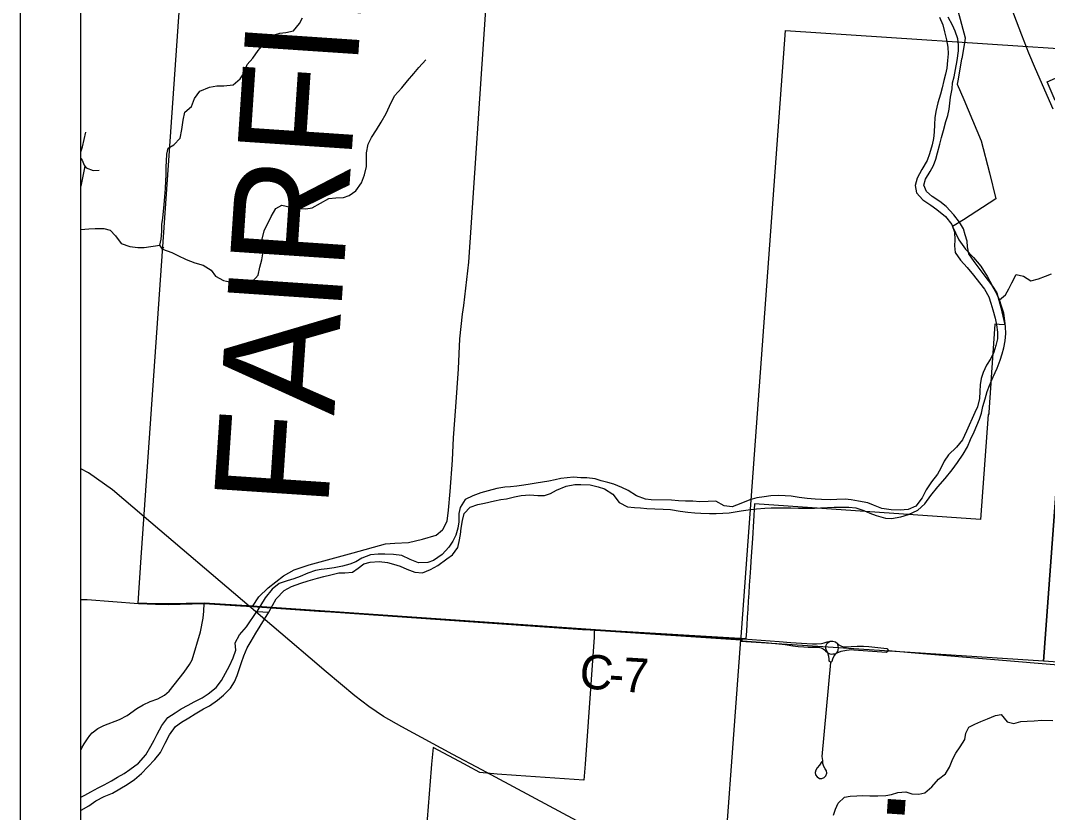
# Model space of a CAD drawing. Extents: x 0 to 34, y 0 to 26.1.
# Drawn here: x 23.417 to 25.117, y 15.919 to 17.231 of the extents above; entities that cross this region are included whole.
import ezdxf

# ---------------------------------------------------------------- set-up
doc = ezdxf.new("R2010")
doc.units = 0
for name, color, linetype in [('GM_X_City_Street', 7, 'Continuous'), ('GM_X_County', 7, 'Continuous'), ('GM_X_County_Road', 7, 'Continuous'), ('GM_X_County_Road_Text', 7, 'Continuous'), ('GM_X_County_Text', 7, 'Continuous'), ('GM_X_Minor_River', 7, 'Continuous'), ('GM_X_Rail_Line', 7, 'Continuous'), ('GM_X_Section', 7, 'Continuous'), ('GM_X_State_Route', 7, 'Continuous'), ('GM_X_Township_Road', 7, 'Continuous'), ('SC_Scratch1', 7, 'Continuous'), ('SH_Data', 7, 'Continuous')]:
    doc.layers.add(name, color=color, linetype=linetype)

msp = doc.modelspace()

# ---------------------------------------------------------------- linework, layer by layer
at = {"layer": 'GM_X_City_Street'}
for p, q in [((23.5233, 16.9894), (23.5167, 16.9562)), ((23.7209, 16.2653), (23.7808, 16.2616)), ((23.7808, 16.2616), (23.7908, 16.261)), ((23.7908, 16.261), (23.8007, 16.2604)), ((23.8007, 16.2604), (23.9105, 16.2528)), ((23.9105, 16.2528), (23.9305, 16.2514)), ((23.9305, 16.2514), (24.2999, 16.2258)), ((24.2999, 16.2258), (24.3468, 16.2225)), ((24.3468, 16.2225), (24.3598, 16.2216))]:
    msp.add_line(p, q, dxfattribs=at)
for points in [[(23.5167, 17.0129), (23.5194, 17.0216), (23.5248, 17.0458)], [(23.5167, 17.0022), (23.5186, 16.9996), (23.5219, 16.9912), (23.5233, 16.9894), (23.5252, 16.9869), (23.5368, 16.9821), (23.5466, 16.9827)], [(23.5167, 16.272), (23.527, 16.2718), (23.6118, 16.2652)], [(23.5167, 16.0227), (23.5184, 16.0266), (23.5222, 16.0332), (23.5273, 16.0412), (23.5313, 16.0468), (23.5353, 16.0513), (23.5448, 16.0582), (23.5545, 16.0633), (23.5804, 16.0735), (23.5932, 16.08), (23.6093, 16.0912), (23.6198, 16.0978), (23.6312, 16.1029), (23.6441, 16.1076), (23.6548, 16.1133), (23.6625, 16.1204), (23.6875, 16.1519), (23.6966, 16.1644), (23.7007, 16.1719), (23.7144, 16.2185), (23.7192, 16.2408), (23.72, 16.2528), (23.7209, 16.2653)], [(23.6118, 16.2652), (23.6401, 16.264), (23.6613, 16.2639), (23.7209, 16.2653)], [(24.3598, 16.2216), (24.3687, 16.221), (24.6093, 16.2051)], [(24.7531, 16.1835), (24.7507, 16.1877), (24.7498, 16.1909), (24.7497, 16.1935), (24.7503, 16.1964), (24.752, 16.1996), (24.7541, 16.2013), (24.757, 16.2028)], [(24.7673, 16.183), (24.7694, 16.1861), (24.7702, 16.1887), (24.7707, 16.1921), (24.7704, 16.1954), (24.769, 16.1993)], [(24.7431, 16.0037), (24.7394, 15.9977), (24.7355, 15.9934), (24.7333, 15.9896), (24.7323, 15.9857), (24.7326, 15.9817), (24.7354, 15.9781), (24.7391, 15.9758), (24.7431, 15.9756), (24.7469, 15.9775), (24.7497, 15.9802), (24.7514, 15.9844), (24.7508, 15.9881), (24.7487, 15.9917), (24.7463, 15.9957), (24.7447, 16.0003), (24.7447, 16.0056), (24.7437, 16.0119), (24.7579, 16.1674)], [(24.7579, 16.1674), (24.7554, 16.17), (24.7551, 16.1738), (24.7546, 16.1777), (24.7531, 16.1835)], [(24.7579, 16.1674), (24.7604, 16.1698), (24.7614, 16.1736), (24.7637, 16.1784), (24.7673, 16.183)]]:
    msp.add_lwpolyline(points, dxfattribs=at)
at = {"layer": 'GM_X_County'}
msp.add_lwpolyline([(24.5371, 15.232), (24.6091, 16.2057), (24.3685, 16.2215), (23.8005, 16.2609), (23.7207, 16.2658), (23.6611, 16.2645), (23.6399, 16.2645), (23.6116, 16.2658), (23.6164, 16.3414), (23.6823, 17.2922), (23.7058, 17.6443), (23.7076, 17.6624), (23.75, 18.3017), (24.7705, 18.2321), (25.2499, 18.1993), (25.6345, 18.1721), (25.7616, 18.1677), (25.9769, 18.149), (26.0141, 18.1458), (26.1801, 18.1381), (26.3977, 18.1227), (26.9793, 18.0768), (27.2717, 18.0608), (27.381, 18.0532)], dxfattribs=at)
at = {"layer": 'GM_X_County_Road'}
for p, q in [((23.7209, 16.2653), (23.7808, 16.2616)), ((23.7808, 16.2616), (23.7908, 16.261)), ((23.7908, 16.261), (23.8007, 16.2604)), ((23.8007, 16.2604), (23.9105, 16.2528)), ((23.9105, 16.2528), (23.9305, 16.2514)), ((23.9305, 16.2514), (24.2999, 16.2258)), ((24.2999, 16.2258), (24.3468, 16.2225)), ((24.3468, 16.2225), (24.3598, 16.2216)), ((24.8534, 16.1873), (24.9039, 16.1831))]:
    msp.add_line(p, q, dxfattribs=at)
for points in [[(24.3598, 16.2216), (24.3687, 16.221), (24.6005, 16.2057), (24.6093, 16.2051)], [(24.6093, 16.2051), (24.6128, 16.2068), (24.6725, 16.2022), (24.692, 16.2008), (24.7093, 16.1996), (24.7274, 16.1983), (24.7345, 16.1984), (24.7424, 16.1993), (24.7468, 16.2004), (24.7521, 16.202), (24.757, 16.2028)], [(24.6093, 16.2051), (24.6118, 16.2035), (24.6493, 16.2009), (24.6722, 16.1985), (24.6824, 16.1972), (24.6949, 16.1955), (24.704, 16.1943), (24.7133, 16.1935), (24.7207, 16.1931), (24.7302, 16.1932), (24.7378, 16.1929), (24.742, 16.192), (24.7451, 16.1905), (24.7476, 16.1886), (24.7492, 16.187), (24.7531, 16.1835)], [(24.757, 16.2028), (24.7613, 16.203), (24.7655, 16.2016), (24.769, 16.1993)], [(24.7673, 16.183), (24.7687, 16.1835), (24.7752, 16.1862), (24.7841, 16.1883), (24.7926, 16.1891), (24.7962, 16.1888), (24.85, 16.1847), (24.8534, 16.1873)], [(24.769, 16.1993), (24.7715, 16.1971), (24.7756, 16.1947), (24.7794, 16.1936), (24.7841, 16.1936), (24.7918, 16.1944), (24.8016, 16.1948), (24.812, 16.1946), (24.8211, 16.194), (24.851, 16.1908), (24.8534, 16.1873)], [(24.7531, 16.1835), (24.7565, 16.182), (24.7592, 16.1817), (24.7614, 16.1818), (24.7647, 16.1821), (24.7673, 16.183)], [(24.9039, 16.1831), (25.2665, 16.153), (25.308, 16.1513)]]:
    msp.add_lwpolyline(points, dxfattribs=at)
at = {"layer": 'GM_X_Minor_River'}
for points in [[(23.6519, 16.8519), (23.6471, 16.8588), (23.6492, 16.8687), (23.6505, 16.8812), (23.6506, 16.8929), (23.6523, 16.9036), (23.6536, 16.9149), (23.6545, 16.9255), (23.6558, 16.9392), (23.6564, 16.9525), (23.6573, 16.9654), (23.6579, 16.9748), (23.6577, 16.9881), (23.6582, 16.9976), (23.6587, 17.0094), (23.6608, 17.0192), (23.6703, 17.0248), (23.6811, 17.036), (23.6839, 17.05), (23.686, 17.0655), (23.6889, 17.0788), (23.6996, 17.0885), (23.7047, 17.1014), (23.7136, 17.1138), (23.7296, 17.1204), (23.7417, 17.1225), (23.7534, 17.1227), (23.7686, 17.124), (23.7805, 17.1341), (23.7867, 17.1442), (23.7918, 17.1578), (23.801, 17.168), (23.8103, 17.1807), (23.8211, 17.1943), (23.8318, 17.2051), (23.8459, 17.2099), (23.8561, 17.2109), (23.8683, 17.2137), (23.8783, 17.2254), (23.8837, 17.2351)], [(24.6097, 16.4188), (24.6214, 16.4206), (24.6347, 16.4219), (24.6487, 16.4229), (24.6593, 16.4235), (24.6695, 16.4237), (24.6809, 16.4239), (24.6919, 16.4238), (24.7044, 16.4232), (24.7199, 16.423), (24.7308, 16.4232), (24.7407, 16.4239), (24.7634, 16.4251), (24.7876, 16.4247), (24.7993, 16.4238), (24.8129, 16.4191), (24.8227, 16.4151), (24.8328, 16.4108), (24.8487, 16.4064), (24.8585, 16.4063), (24.8737, 16.4087), (24.8866, 16.4127), (24.9019, 16.4201), (24.9134, 16.4306), (24.9234, 16.4441), (24.9353, 16.4587), (24.9473, 16.4722), (24.9588, 16.4869), (24.9677, 16.4989), (24.9773, 16.5124), (24.984, 16.5249), (24.9894, 16.5366), (24.9953, 16.5498), (24.9996, 16.5603), (25.0039, 16.5705), (25.0075, 16.5807), (25.0099, 16.5913), (25.0135, 16.6042), (25.017, 16.6163), (25.0206, 16.6265), (25.0265, 16.6404), (25.0331, 16.6548), (25.0386, 16.668), (25.0418, 16.6786), (25.0442, 16.6884), (25.0466, 16.7001), (25.0476, 16.7126), (25.0473, 16.7233), (25.0463, 16.7335), (25.0442, 16.7461), (25.041, 16.756), (25.0374, 16.7682), (25.0308, 16.7827), (25.0245, 16.7927), (25.0133, 16.8072), (25.0033, 16.8203), (24.9951, 16.8314), (24.9866, 16.8441), (24.9841, 16.8559), (24.9835, 16.8654), (24.9806, 16.876), (24.9777, 16.8859), (24.9711, 16.8967), (24.9614, 16.9086), (24.9491, 16.9228), (24.9383, 16.9309), (24.9259, 16.9394), (24.9162, 16.9475), (24.9118, 16.9578), (24.915, 16.968), (24.9227, 16.9805), (24.9278, 16.9903), (24.9317, 17.0012), (24.9345, 17.0114), (24.9385, 17.0258), (24.9413, 17.0371), (24.9445, 17.0485), (24.9485, 17.0636), (24.9517, 17.0734), (24.9537, 17.084), (24.955, 17.0935), (24.9562, 17.1037), (24.9587, 17.1177), (24.9596, 17.1276), (24.9624, 17.1374), (24.9645, 17.1496), (24.9673, 17.1643), (24.9694, 17.1802), (24.9692, 17.1901), (24.9682, 17.2), (24.9639, 17.213), (24.9595, 17.2229), (24.9525, 17.2363)], [(24.9381, 17.2361), (24.9436, 17.2235), (24.9464, 17.2121), (24.9493, 17.1987), (24.9517, 17.1862), (24.952, 17.1752), (24.9514, 17.1642), (24.9501, 17.1517), (24.9477, 17.1418), (24.9449, 17.1312), (24.9425, 17.1191), (24.9393, 17.1085), (24.9353, 17.0942), (24.9321, 17.0798), (24.9304, 17.0696), (24.9299, 17.0586), (24.9293, 17.046), (24.928, 17.0354), (24.926, 17.0248), (24.9212, 17.0097), (24.9173, 16.9988), (24.9084, 16.9837), (24.901, 16.9694), (24.8978, 16.9573), (24.8999, 16.9451), (24.9103, 16.9339), (24.9234, 16.9246), (24.9335, 16.9177), (24.9478, 16.9061), (24.9582, 16.893), (24.9625, 16.8801), (24.9631, 16.8672), (24.963, 16.8577), (24.9636, 16.8467), (24.9725, 16.8336), (24.9836, 16.8217), (24.9941, 16.809), (25.0041, 16.796), (25.0123, 16.786), (25.0197, 16.773), (25.0229, 16.7627), (25.0262, 16.7517), (25.0301, 16.7379), (25.0322, 16.7269), (25.034, 16.7147), (25.0338, 16.7033), (25.0314, 16.6927), (25.0278, 16.6814), (25.0231, 16.6712), (25.0158, 16.6599), (25.0103, 16.6479), (25.0071, 16.6377), (25.0055, 16.6274), (25.0046, 16.6161), (25.004, 16.6047), (25.0008, 16.5911), (24.9965, 16.5813), (24.9824, 16.5507), (24.9762, 16.5364), (24.9662, 16.524), (24.9527, 16.5113)], [(23.6533, 16.8551), (23.6519, 16.8519), (23.667, 16.8464), (23.6772, 16.8417), (23.6907, 16.8347), (23.705, 16.8292), (23.7189, 16.8256), (23.7321, 16.817), (23.7395, 16.8074), (23.7526, 16.8001), (23.7628, 16.798), (23.7749, 16.7963), (23.7882, 16.7965), (23.8007, 16.7986), (23.8099, 16.8087), (23.8127, 16.822), (23.8163, 16.8345), (23.818, 16.8443), (23.817, 16.8553), (23.8164, 16.8686), (23.8197, 16.8826), (23.8317, 16.906), (23.8391, 16.9196), (23.849, 16.9251), (23.8634, 16.9215), (23.8754, 16.9191), (23.889, 16.9189), (23.8997, 16.9206), (23.9134, 16.928), (23.9271, 16.9358), (23.9385, 16.9368), (23.9514, 16.9374), (23.9609, 16.9406), (23.9716, 16.9485), (23.9809, 16.9616), (23.986, 16.9752), (23.9892, 16.9888), (23.9895, 17.0116), (23.9924, 17.0256), (23.9978, 17.0369), (24.006, 17.0497), (24.0137, 17.0625), (24.0222, 17.0765), (24.0277, 17.0889), (24.0359, 17.1059), (24.0478, 17.1194), (24.0571, 17.1306), (24.0675, 17.1426), (24.0759, 17.1528), (24.0875, 17.1655)], [(23.5167, 16.8847), (23.5299, 16.8858), (23.5401, 16.8861), (23.5544, 16.8864), (23.565, 16.8837), (23.574, 16.8742), (23.5834, 16.8616), (23.5977, 16.8562), (23.6106, 16.8546), (23.6212, 16.8549), (23.6471, 16.8588)], [(25.0374, 16.7682), (25.0473, 16.7764), (25.0528, 16.7866), (25.0575, 16.7964), (25.0648, 16.8099), (25.0769, 16.8075), (25.0893, 16.7994), (25.1018, 16.803), (25.1132, 16.8074), (25.1231, 16.8114)], [(24.9527, 16.5113), (24.9454, 16.5011), (24.9399, 16.4894), (24.9345, 16.4796), (24.9248, 16.4669), (24.9156, 16.4533), (24.9093, 16.4405), (24.8989, 16.4266), (24.886, 16.4211), (24.8727, 16.4201), (24.858, 16.4203), (24.8425, 16.4225), (24.8289, 16.428), (24.8191, 16.4319), (24.804, 16.4347), (24.7916, 16.4372), (24.7818, 16.4381), (24.7681, 16.4375), (24.7572, 16.4369), (24.7428, 16.4375), (24.7322, 16.438), (24.719, 16.4393), (24.7057, 16.441), (24.6921, 16.4428), (24.6823, 16.4436), (24.6717, 16.4442), (24.6589, 16.4436), (24.6475, 16.4422), (24.6357, 16.4405), (24.6239, 16.4372), (24.6091, 16.431), (24.5946, 16.4255), (24.5814, 16.4272), (24.5679, 16.435), (24.555, 16.434), (24.5414, 16.4338), (24.5297, 16.4348), (24.5176, 16.4345), (24.5058, 16.4355), (24.4945, 16.4364), (24.4608, 16.4368), (24.451, 16.4381), (24.4363, 16.4436), (24.4228, 16.4522), (24.4123, 16.4576), (24.3988, 16.4628), (24.389, 16.4656), (24.3776, 16.4687), (24.3679, 16.4719), (24.3539, 16.4733), (24.344, 16.4734), (24.3319, 16.4743), (24.3213, 16.4733), (24.3111, 16.4723), (24.3016, 16.4702), (24.291, 16.4681), (24.2807, 16.4663), (24.2701, 16.4645), (24.2602, 16.4628), (24.25, 16.4614), (24.2383, 16.4597), (24.228, 16.4587), (24.2185, 16.4577), (24.2053, 16.4556), (24.1905, 16.4516), (24.1787, 16.4484), (24.1654, 16.4436), (24.1528, 16.4373), (24.1447, 16.4245), (24.1422, 16.4143), (24.142, 16.4003), (24.1408, 16.39), (24.1372, 16.3783), (24.1321, 16.3685), (24.1255, 16.3584), (24.1148, 16.3464), (24.1003, 16.3367), (24.0908, 16.3334), (24.0752, 16.3325), (24.0617, 16.338), (24.0478, 16.3447), (24.0338, 16.3464), (24.0198, 16.3469), (24.0088, 16.3471), (23.9959, 16.3458), (23.9819, 16.3403), (23.9716, 16.3343), (23.962, 16.3307), (23.9499, 16.3274), (23.9358, 16.3246), (23.9241, 16.3228), (23.9146, 16.3218), (23.9051, 16.3197), (23.8922, 16.3153), (23.8796, 16.3102), (23.869, 16.3061), (23.8579, 16.3029), (23.845, 16.2985), (23.8332, 16.2888), (23.8216, 16.2745), (23.8079, 16.2522)], [(23.8279, 16.2509), (23.8401, 16.2731), (23.8528, 16.2866), (23.8654, 16.2933), (23.8806, 16.2991), (23.8928, 16.3028), (23.908, 16.3075), (23.9186, 16.31), (23.9304, 16.3129), (23.9433, 16.3161), (23.9535, 16.316), (23.966, 16.3173), (23.9756, 16.324), (23.9851, 16.3311), (23.9954, 16.3336), (24.0105, 16.3349), (24.0241, 16.3332), (24.0343, 16.3304), (24.0449, 16.3269), (24.0562, 16.3221), (24.0693, 16.3174), (24.0822, 16.3161), (24.0955, 16.3216), (24.1077, 16.3283), (24.1222, 16.3391), (24.1318, 16.3461), (24.1407, 16.3582), (24.1427, 16.368), (24.1448, 16.3794), (24.1461, 16.39), (24.1485, 16.4025), (24.1513, 16.4142), (24.1609, 16.4251), (24.1735, 16.4291), (24.1845, 16.4316), (24.2012, 16.4355), (24.2118, 16.4373), (24.2213, 16.4387), (24.2346, 16.4419), (24.2456, 16.4444), (24.2596, 16.445), (24.2732, 16.4444), (24.2838, 16.4442), (24.2937, 16.4475), (24.304, 16.4527), (24.32, 16.4597), (24.334, 16.4621), (24.3443, 16.4624), (24.3594, 16.4618), (24.373, 16.4586), (24.3831, 16.455), (24.3974, 16.4461), (24.4074, 16.4327), (24.4213, 16.4253), (24.433, 16.424), (24.4429, 16.4238), (24.4534, 16.4225), (24.4667, 16.422), (24.4807, 16.4214), (24.4924, 16.4208), (24.5086, 16.4183), (24.5215, 16.4167), (24.5328, 16.4154), (24.5426, 16.4148), (24.5574, 16.4143), (24.568, 16.4141), (24.579, 16.4147), (24.5896, 16.4153), (24.5998, 16.4171), (24.6097, 16.4188)], [(23.5167, 15.9448), (23.5233, 15.9481), (23.5332, 15.9537), (23.5453, 15.9601), (23.5552, 15.9653), (23.5673, 15.9717), (23.5772, 15.9777), (23.5882, 15.9841), (23.5977, 15.9905), (23.6121, 16.001), (23.6243, 16.015), (23.6324, 16.029), (23.6381, 16.0388), (23.6427, 16.0487), (23.6507, 16.0634), (23.6606, 16.0763), (23.6724, 16.0845), (23.6827, 16.0909), (23.6944, 16.0969), (23.7039, 16.1026), (23.7172, 16.1093), (23.7274, 16.1157), (23.7404, 16.1262), (23.7491, 16.138), (23.756, 16.1497), (23.7625, 16.1622), (23.7686, 16.1754), (23.7729, 16.1879), (23.7722, 16.2001), (23.7791, 16.2133), (23.7909, 16.2269), (23.8079, 16.2522)], [(23.8079, 16.2522), (23.8279, 16.2509)], [(23.5167, 15.9229), (23.5171, 15.9231), (23.5296, 15.9302), (23.5414, 15.9385), (23.5551, 15.9456), (23.5687, 15.9512), (23.5809, 15.9584), (23.593, 15.9659), (23.6052, 15.9738), (23.617, 15.9839), (23.6272, 15.9949), (23.639, 16.0073), (23.6486, 16.0187), (23.6562, 16.0342), (23.6631, 16.0478), (23.6734, 16.0618), (23.6833, 16.0689), (23.695, 16.0761), (23.7057, 16.0828), (23.7193, 16.0907), (23.7292, 16.096), (23.7429, 16.105), (23.7524, 16.1133), (23.7645, 16.125), (23.771, 16.1355), (23.7753, 16.1461), (23.7826, 16.1677), (23.7864, 16.1787), (23.7918, 16.192), (23.7983, 16.2029), (23.806, 16.2162), (23.8279, 16.2509)], [(24.7626, 15.915), (24.7658, 15.9248), (24.7701, 15.935), (24.7804, 15.9447), (24.7903, 15.9465), (24.8009, 15.9471), (24.8107, 15.9473), (24.8228, 15.9471), (24.8357, 15.9466), (24.849, 15.9472), (24.8584, 15.9489), (24.8691, 15.9526), (24.8823, 15.9535), (24.8921, 15.9504), (24.9035, 15.9494), (24.9134, 15.9516), (24.9252, 15.9617), (24.9364, 15.9744), (24.9479, 15.9834), (24.9545, 15.9943), (24.9599, 16.0079), (24.965, 16.0177), (24.9723, 16.0282), (24.9797, 16.0402), (24.9814, 16.0505), (24.9864, 16.0603), (24.9963, 16.0658), (25.0066, 16.0702), (25.0173, 16.0746), (25.0306, 16.0801), (25.0401, 16.0815), (25.0501, 16.0693), (25.0607, 16.0665), (25.0728, 16.0697), (25.0831, 16.0707), (25.0948, 16.0713), (25.1073, 16.0719), (25.1254, 16.0714)]]:
    msp.add_lwpolyline(points, dxfattribs=at)
at = {"layer": 'GM_X_Rail_Line'}
for points in [[(23.6212, 16.4087), (23.5687, 16.4538), (23.5293, 16.4815), (23.5167, 16.4885)], [(23.7982, 16.2582), (23.7954, 16.2607), (23.6212, 16.4087)], [(24.5774, 15.7768), (24.4384, 15.8515), (24.315, 15.9174), (24.1803, 15.9897), (24.1325, 16.0154), (24.0479, 16.0609), (24.0177, 16.0785), (23.9935, 16.0947), (23.9701, 16.1123), (23.9224, 16.1522), (23.896, 16.175), (23.8622, 16.2036), (23.8327, 16.2287), (23.7982, 16.2582)]]:
    msp.add_lwpolyline(points, dxfattribs=at)
at = {"layer": 'GM_X_Section'}
for points in [[(24.6829, 17.2138), (25.1844, 17.1812), (25.1103, 16.1697), (24.6093, 16.2025)], [(25.1844, 17.1812), (25.6903, 17.1467), (25.6194, 16.135), (25.1103, 16.1697)]]:
    msp.add_lwpolyline(points, close=True, dxfattribs=at)
at = {"layer": 'GM_X_State_Route'}
msp.add_lwpolyline([(25.054, 17.2576), (25.0558, 17.253), (25.0734, 17.207), (25.0852, 17.1772), (25.0964, 17.151), (25.1253, 17.0843)], dxfattribs=at)
at = {"layer": 'GM_X_Township_Road'}
msp.add_lwpolyline([(23.8007, 16.2604), (23.8112, 16.2762), (23.8265, 16.2914), (23.8517, 16.3113), (23.8698, 16.321), (23.8944, 16.3294), (23.9671, 16.3494), (24.0206, 16.3641), (24.0362, 16.365), (24.059, 16.3664), (24.0818, 16.372), (24.1046, 16.3787), (24.1153, 16.3871), (24.116, 16.3877), (24.123, 16.4014), (24.125, 16.4196), (24.1278, 16.4508), (24.1316, 16.5029), (24.1333, 16.5394), (24.1374, 16.5907), (24.1416, 16.6538), (24.1438, 16.7036), (24.1485, 16.7443), (24.1503, 16.759), (24.1588, 16.8304), (24.1867, 17.2491)], dxfattribs=at)
at = {"layer": 'SC_Scratch1'}
for points in [[(24.9684, 17.2469), (24.9806, 17.2021), (24.9797, 17.1967), (24.9747, 17.1677), (24.9745, 17.167), (24.9688, 17.1337), (24.9673, 17.1253), (24.9782, 17.0997), (25.007, 17.0313), (25.0205, 16.9782), (25.0313, 16.9355), (24.9774, 16.9007), (24.9597, 16.8893), (24.9699, 16.8673), (24.981, 16.8519), (24.9941, 16.838), (25.0065, 16.8236), (25.0136, 16.8124), (25.0166, 16.8075), (25.0257, 16.7908), (25.0329, 16.7796), (25.0396, 16.7554), (25.0459, 16.7267), (25.0459, 16.7266), (25.0458, 16.7267), (25.0366, 16.7273), (25.0296, 16.7278), (25.0295, 16.7279), (25.0295, 16.7278), (25.0231, 16.6319), (25.023, 16.6304), (25.0209, 16.5982), (25.0196, 16.5817), (25.0196, 16.581), (25.0194, 16.5782), (25.0185, 16.5783), (25.0059, 16.4042), (24.6319, 16.4301), (24.6282, 16.3732), (24.6262, 16.3434), (24.6257, 16.3346), (24.625, 16.3245), (24.624, 16.3089), (24.6231, 16.2957), (24.6223, 16.2825), (24.6214, 16.2692), (24.6205, 16.256), (24.6197, 16.2428), (24.6188, 16.2296), (24.6177, 16.2125), (24.6175, 16.2087), (24.6173, 16.2066), (24.3835, 16.2206), (24.3669, 16.2216), (24.3665, 16.2178), (24.366, 16.2098), (24.3512, 15.9991), (24.3494, 15.9728), (24.237, 15.9806), (24.2057, 15.9827), (24.1771, 15.9855), (24.1565, 15.9966), (24.1518, 15.9991), (24.0997, 16.0268), (24.0972, 15.9991), (24.0966, 15.9919), (24.0851, 15.8452)], [(25.1296, 17.0981), (25.116, 17.1293), (25.1397, 17.1396)]]:
    msp.add_lwpolyline(points, dxfattribs=at)
at = {"layer": 'SH_Data'}
for points in [[(23.4167, 21), (30.4167, 21), (30.4167, 14), (23.4167, 14)], [(23.5167, 20.9), (30.3167, 20.9), (30.3167, 14.1), (23.5167, 14.1)]]:
    msp.add_lwpolyline(points, close=True, dxfattribs=at)

# ---------------------------------------------------------------- texts
at = {"layer": 'GM_X_County_Road_Text'}
for s, rotation, p in [('C', 353.4404, (24.3396, 16.1266)), ('7', 356.5399, (24.4126, 16.1195)), ('-', 356.4281, (24.3892, 16.121))]:
    msp.add_text(s, height=0.0568, rotation=rotation, dxfattribs=at).set_placement(p)
at = {"layer": 'GM_X_County_Text'}
for p in [(23.9254, 16.4215), (24.7619, 14.1516)]:
    msp.add_text('FAIRFIELD CO.', height=0.189394, rotation=86.1646, dxfattribs=at).set_placement(p)

doc.saveas('drawing.dxf')
